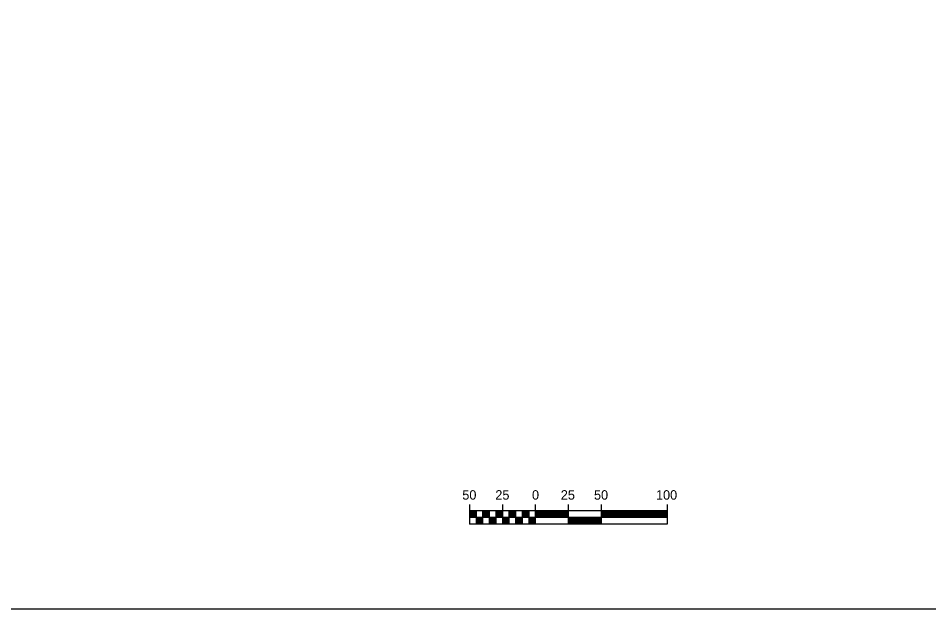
# Model space of a CAD drawing. Extents: x 1806834 to 1810084, y 678065 to 679314.
# Drawn here: x 1807616 to 1808308, y 678065 to 678514 of the extents above; entities that cross this region are included whole.
import ezdxf

# ---------------------------------------------------------------- set-up
doc = ezdxf.new("R2010")
doc.units = 0
doc.layers.add('Default', color=7, linetype='Continuous')
doc.layers.add('DSN_DRFT_Guideline-No-Plot', color=7, linetype='Continuous')

msp = doc.modelspace()

# ---------------------------------------------------------------- linework, layer by layer
at = {"layer": 'Default'}
for p, q in [((1807958.81, 678144.7), (1807958.81, 678129.7)), ((1807983.81, 678144.7), (1807983.81, 678129.7)), ((1808008.81, 678144.7), (1808008.81, 678129.7)), ((1808033.81, 678144.7), (1808033.81, 678129.7)), ((1808058.81, 678144.7), (1808058.81, 678129.7)), ((1808108.8, 678144.7), (1808108.8, 678129.7)), ((1808108.8, 678139.7), (1807958.81, 678139.7)), ((1807958.81, 678139.45), (1807963.81, 678139.45)), ((1807958.81, 678139.2), (1807963.81, 678139.2)), ((1807958.81, 678138.95), (1807963.81, 678138.95)), ((1807958.81, 678138.7), (1807963.81, 678138.7)), ((1807958.81, 678138.45), (1807963.81, 678138.45)), ((1807958.81, 678138.2), (1807963.81, 678138.2)), ((1807958.81, 678137.95), (1807963.81, 678137.95)), ((1807958.81, 678137.7), (1807963.81, 678137.7)), ((1807958.81, 678137.45), (1807963.81, 678137.45)), ((1807958.81, 678137.2), (1807963.81, 678137.2)), ((1807958.81, 678136.95), (1807963.81, 678136.95)), ((1807958.81, 678136.7), (1807963.81, 678136.7)), ((1807958.81, 678136.45), (1807963.81, 678136.45)), ((1807958.81, 678136.2), (1807963.81, 678136.2)), ((1807958.81, 678135.95), (1807963.81, 678135.95)), ((1807958.81, 678135.7), (1807963.81, 678135.7)), ((1807958.81, 678135.45), (1807963.81, 678135.45)), ((1807958.81, 678135.2), (1807963.81, 678135.2)), ((1807958.81, 678134.95), (1807963.81, 678134.95)), ((1808108.8, 678134.7), (1807958.81, 678134.7)), ((1807963.81, 678139.7), (1807963.81, 678129.7)), ((1807968.81, 678139.7), (1807968.81, 678129.7)), ((1807968.81, 678139.45), (1807973.81, 678139.45)), ((1807968.81, 678139.2), (1807973.81, 678139.2)), ((1807968.81, 678138.95), (1807973.81, 678138.95)), ((1807968.81, 678138.7), (1807973.81, 678138.7)), ((1807968.81, 678138.45), (1807973.81, 678138.45)), ((1807968.81, 678138.2), (1807973.81, 678138.2)), ((1807968.81, 678137.95), (1807973.81, 678137.95)), ((1807968.81, 678137.7), (1807973.81, 678137.7)), ((1807968.81, 678137.45), (1807973.81, 678137.45)), ((1807968.81, 678137.2), (1807973.81, 678137.2)), ((1807968.81, 678136.95), (1807973.81, 678136.95)), ((1807968.81, 678136.7), (1807973.81, 678136.7)), ((1807968.81, 678136.45), (1807973.81, 678136.45)), ((1807968.81, 678136.2), (1807973.81, 678136.2)), ((1807968.81, 678135.95), (1807973.81, 678135.95)), ((1807968.81, 678135.7), (1807973.81, 678135.7)), ((1807968.81, 678135.45), (1807973.81, 678135.45)), ((1807968.81, 678135.2), (1807973.81, 678135.2)), ((1807968.81, 678134.95), (1807973.81, 678134.95)), ((1807973.81, 678139.7), (1807973.81, 678129.7)), ((1807978.81, 678139.7), (1807978.81, 678129.7)), ((1807978.81, 678139.45), (1807983.81, 678139.45)), ((1807978.81, 678139.2), (1807983.81, 678139.2)), ((1807978.81, 678138.95), (1807983.81, 678138.95)), ((1807978.81, 678138.7), (1807983.81, 678138.7)), ((1807978.81, 678138.45), (1807983.81, 678138.45)), ((1807978.81, 678138.2), (1807983.81, 678138.2)), ((1807978.81, 678137.95), (1807983.81, 678137.95)), ((1807978.81, 678137.7), (1807983.81, 678137.7)), ((1807978.81, 678137.45), (1807983.81, 678137.45)), ((1807978.81, 678137.2), (1807983.81, 678137.2)), ((1807978.81, 678136.95), (1807983.81, 678136.95)), ((1807978.81, 678136.7), (1807983.81, 678136.7)), ((1807978.81, 678136.45), (1807983.81, 678136.45)), ((1807978.81, 678136.2), (1807983.81, 678136.2)), ((1807978.81, 678135.95), (1807983.81, 678135.95)), ((1807978.81, 678135.7), (1807983.81, 678135.7)), ((1807978.81, 678135.45), (1807983.81, 678135.45)), ((1807978.81, 678135.2), (1807983.81, 678135.2)), ((1807978.81, 678134.95), (1807983.81, 678134.95)), ((1807988.81, 678139.7), (1807988.81, 678129.7)), ((1807988.81, 678139.45), (1807993.81, 678139.45)), ((1807988.81, 678139.2), (1807993.81, 678139.2)), ((1807988.81, 678138.95), (1807993.81, 678138.95)), ((1807988.81, 678138.7), (1807993.81, 678138.7)), ((1807988.81, 678138.45), (1807993.81, 678138.45)), ((1807988.81, 678138.2), (1807993.81, 678138.2)), ((1807988.81, 678137.95), (1807993.81, 678137.95)), ((1807988.81, 678137.7), (1807993.81, 678137.7)), ((1807988.81, 678137.45), (1807993.81, 678137.45)), ((1807988.81, 678137.2), (1807993.81, 678137.2)), ((1807988.81, 678136.95), (1807993.81, 678136.95)), ((1807988.81, 678136.7), (1807993.81, 678136.7)), ((1807988.81, 678136.45), (1807993.81, 678136.45)), ((1807988.81, 678136.2), (1807993.81, 678136.2)), ((1807988.81, 678135.95), (1807993.81, 678135.95)), ((1807988.81, 678135.7), (1807993.81, 678135.7)), ((1807988.81, 678135.45), (1807993.81, 678135.45)), ((1807988.81, 678135.2), (1807993.81, 678135.2)), ((1807988.81, 678134.95), (1807993.81, 678134.95)), ((1807993.81, 678139.7), (1807993.81, 678129.7)), ((1807998.81, 678139.7), (1807998.81, 678129.7)), ((1807998.81, 678139.45), (1808003.81, 678139.45)), ((1807998.81, 678139.2), (1808003.81, 678139.2)), ((1807998.81, 678138.95), (1808003.81, 678138.95)), ((1807998.81, 678138.7), (1808003.81, 678138.7)), ((1807998.81, 678138.45), (1808003.81, 678138.45)), ((1807998.81, 678138.2), (1808003.81, 678138.2)), ((1807998.81, 678137.95), (1808003.81, 678137.95)), ((1807998.81, 678137.7), (1808003.81, 678137.7)), ((1807998.81, 678137.45), (1808003.81, 678137.45)), ((1807998.81, 678137.2), (1808003.81, 678137.2)), ((1807998.81, 678136.95), (1808003.81, 678136.95)), ((1807998.81, 678136.7), (1808003.81, 678136.7)), ((1807998.81, 678136.45), (1808003.81, 678136.45)), ((1807998.81, 678136.2), (1808003.81, 678136.2)), ((1807998.81, 678135.95), (1808003.81, 678135.95)), ((1807998.81, 678135.7), (1808003.81, 678135.7)), ((1807998.81, 678135.45), (1808003.81, 678135.45)), ((1807998.81, 678135.2), (1808003.81, 678135.2)), ((1807998.81, 678134.95), (1808003.81, 678134.95)), ((1808003.81, 678139.7), (1808003.81, 678129.7)), ((1808033.81, 678139.45), (1808008.81, 678139.45)), ((1808033.81, 678139.2), (1808008.81, 678139.2)), ((1808033.81, 678138.95), (1808008.81, 678138.95)), ((1808033.81, 678138.7), (1808008.81, 678138.7)), ((1808033.81, 678138.45), (1808008.81, 678138.45)), ((1808033.81, 678138.2), (1808008.81, 678138.2)), ((1808033.81, 678137.95), (1808008.81, 678137.95)), ((1808033.81, 678137.7), (1808008.81, 678137.7)), ((1808033.81, 678137.45), (1808008.81, 678137.45)), ((1808033.81, 678137.2), (1808008.81, 678137.2)), ((1808033.81, 678136.95), (1808008.81, 678136.95)), ((1808033.81, 678136.7), (1808008.81, 678136.7)), ((1808033.81, 678136.45), (1808008.81, 678136.45)), ((1808033.81, 678136.2), (1808008.81, 678136.2)), ((1808033.81, 678135.95), (1808008.81, 678135.95)), ((1808033.81, 678135.7), (1808008.81, 678135.7)), ((1808033.81, 678135.45), (1808008.81, 678135.45)), ((1808033.81, 678135.2), (1808008.81, 678135.2)), ((1808033.81, 678134.95), (1808008.81, 678134.95)), ((1808058.81, 678139.45), (1808108.8, 678139.45)), ((1808058.81, 678139.2), (1808108.8, 678139.2)), ((1808058.81, 678138.95), (1808108.8, 678138.95)), ((1808058.81, 678138.7), (1808108.8, 678138.7)), ((1808058.81, 678138.45), (1808108.8, 678138.45)), ((1808058.81, 678138.2), (1808108.8, 678138.2)), ((1808058.81, 678137.95), (1808108.8, 678137.95)), ((1808058.81, 678137.7), (1808108.8, 678137.7)), ((1808058.81, 678137.45), (1808108.8, 678137.45)), ((1808058.81, 678137.2), (1808108.8, 678137.2)), ((1808058.81, 678136.95), (1808108.8, 678136.95)), ((1808058.81, 678136.7), (1808108.8, 678136.7)), ((1808058.81, 678136.45), (1808108.8, 678136.45)), ((1808058.81, 678136.2), (1808108.8, 678136.2)), ((1808058.81, 678135.95), (1808108.8, 678135.95)), ((1808058.81, 678135.7), (1808108.8, 678135.7)), ((1808058.81, 678135.45), (1808108.8, 678135.45)), ((1808058.81, 678135.2), (1808108.8, 678135.2)), ((1808058.81, 678134.95), (1808108.8, 678134.95)), ((1808108.8, 678129.7), (1807958.81, 678129.7)), ((1807963.81, 678134.45), (1807968.81, 678134.45)), ((1807963.81, 678134.2), (1807968.81, 678134.2)), ((1807963.81, 678133.95), (1807968.81, 678133.95)), ((1807963.81, 678133.7), (1807968.81, 678133.7)), ((1807963.81, 678133.45), (1807968.81, 678133.45)), ((1807963.81, 678133.2), (1807968.81, 678133.2)), ((1807963.81, 678132.95), (1807968.81, 678132.95)), ((1807963.81, 678132.7), (1807968.81, 678132.7)), ((1807963.81, 678132.45), (1807968.81, 678132.45)), ((1807963.81, 678132.2), (1807968.81, 678132.2)), ((1807963.81, 678131.95), (1807968.81, 678131.95)), ((1807963.81, 678131.7), (1807968.81, 678131.7)), ((1807963.81, 678131.45), (1807968.81, 678131.45)), ((1807963.81, 678131.2), (1807968.81, 678131.2)), ((1807963.81, 678130.95), (1807968.81, 678130.95)), ((1807963.81, 678130.7), (1807968.81, 678130.7)), ((1807963.81, 678130.45), (1807968.81, 678130.45)), ((1807963.81, 678130.2), (1807968.81, 678130.2)), ((1807963.81, 678129.95), (1807968.81, 678129.95)), ((1807973.81, 678134.45), (1807978.81, 678134.45)), ((1807973.81, 678134.2), (1807978.81, 678134.2)), ((1807973.81, 678133.95), (1807978.81, 678133.95)), ((1807973.81, 678133.7), (1807978.81, 678133.7)), ((1807973.81, 678133.45), (1807978.81, 678133.45)), ((1807973.81, 678133.2), (1807978.81, 678133.2)), ((1807973.81, 678132.95), (1807978.81, 678132.95)), ((1807973.81, 678132.7), (1807978.81, 678132.7)), ((1807973.81, 678132.45), (1807978.81, 678132.45)), ((1807973.81, 678132.2), (1807978.81, 678132.2)), ((1807973.81, 678131.95), (1807978.81, 678131.95)), ((1807973.81, 678131.7), (1807978.81, 678131.7)), ((1807973.81, 678131.45), (1807978.81, 678131.45)), ((1807973.81, 678131.2), (1807978.81, 678131.2)), ((1807973.81, 678130.95), (1807978.81, 678130.95)), ((1807973.81, 678130.7), (1807978.81, 678130.7)), ((1807973.81, 678130.45), (1807978.81, 678130.45)), ((1807973.81, 678130.2), (1807978.81, 678130.2)), ((1807973.81, 678129.95), (1807978.81, 678129.95)), ((1807983.81, 678134.45), (1807988.81, 678134.45)), ((1807983.81, 678134.2), (1807988.81, 678134.2)), ((1807983.81, 678133.95), (1807988.81, 678133.95)), ((1807983.81, 678133.7), (1807988.81, 678133.7)), ((1807983.81, 678133.45), (1807988.81, 678133.45)), ((1807983.81, 678133.2), (1807988.81, 678133.2)), ((1807983.81, 678132.95), (1807988.81, 678132.95)), ((1807983.81, 678132.7), (1807988.81, 678132.7)), ((1807983.81, 678132.45), (1807988.81, 678132.45)), ((1807983.81, 678132.2), (1807988.81, 678132.2)), ((1807983.81, 678131.95), (1807988.81, 678131.95)), ((1807983.81, 678131.7), (1807988.81, 678131.7)), ((1807983.81, 678131.45), (1807988.81, 678131.45)), ((1807983.81, 678131.2), (1807988.81, 678131.2)), ((1807983.81, 678130.95), (1807988.81, 678130.95)), ((1807983.81, 678130.7), (1807988.81, 678130.7)), ((1807983.81, 678130.45), (1807988.81, 678130.45)), ((1807983.81, 678130.2), (1807988.81, 678130.2)), ((1807983.81, 678129.95), (1807988.81, 678129.95)), ((1807993.81, 678134.45), (1807998.81, 678134.45)), ((1807993.81, 678134.2), (1807998.81, 678134.2)), ((1807993.81, 678133.95), (1807998.81, 678133.95)), ((1807993.81, 678133.7), (1807998.81, 678133.7)), ((1807993.81, 678133.45), (1807998.81, 678133.45)), ((1807993.81, 678133.2), (1807998.81, 678133.2)), ((1807993.81, 678132.95), (1807998.81, 678132.95)), ((1807993.81, 678132.7), (1807998.81, 678132.7)), ((1807993.81, 678132.45), (1807998.81, 678132.45)), ((1807993.81, 678132.2), (1807998.81, 678132.2)), ((1807993.81, 678131.95), (1807998.81, 678131.95)), ((1807993.81, 678131.7), (1807998.81, 678131.7)), ((1807993.81, 678131.45), (1807998.81, 678131.45)), ((1807993.81, 678131.2), (1807998.81, 678131.2)), ((1807993.81, 678130.95), (1807998.81, 678130.95)), ((1807993.81, 678130.7), (1807998.81, 678130.7)), ((1807993.81, 678130.45), (1807998.81, 678130.45)), ((1807993.81, 678130.2), (1807998.81, 678130.2)), ((1807993.81, 678129.95), (1807998.81, 678129.95)), ((1808003.81, 678134.45), (1808008.81, 678134.45)), ((1808003.81, 678134.2), (1808008.81, 678134.2)), ((1808003.81, 678133.95), (1808008.81, 678133.95)), ((1808003.81, 678133.7), (1808008.81, 678133.7)), ((1808003.81, 678133.45), (1808008.81, 678133.45)), ((1808003.81, 678133.2), (1808008.81, 678133.2)), ((1808003.81, 678132.95), (1808008.81, 678132.95)), ((1808003.81, 678132.7), (1808008.81, 678132.7)), ((1808003.81, 678132.45), (1808008.81, 678132.45)), ((1808003.81, 678132.2), (1808008.81, 678132.2)), ((1808003.81, 678131.95), (1808008.81, 678131.95)), ((1808003.81, 678131.7), (1808008.81, 678131.7)), ((1808003.81, 678131.45), (1808008.81, 678131.45)), ((1808003.81, 678131.2), (1808008.81, 678131.2)), ((1808003.81, 678130.95), (1808008.81, 678130.95)), ((1808003.81, 678130.7), (1808008.81, 678130.7)), ((1808003.81, 678130.45), (1808008.81, 678130.45)), ((1808003.81, 678130.2), (1808008.81, 678130.2)), ((1808003.81, 678129.95), (1808008.81, 678129.95)), ((1808058.81, 678134.45), (1808033.81, 678134.45)), ((1808058.81, 678134.2), (1808033.81, 678134.2)), ((1808058.81, 678133.95), (1808033.81, 678133.95)), ((1808058.81, 678133.7), (1808033.81, 678133.7)), ((1808058.81, 678133.45), (1808033.81, 678133.45)), ((1808058.81, 678133.2), (1808033.81, 678133.2)), ((1808058.81, 678132.95), (1808033.81, 678132.95)), ((1808058.81, 678132.7), (1808033.81, 678132.7)), ((1808058.81, 678132.45), (1808033.81, 678132.45)), ((1808058.81, 678132.2), (1808033.81, 678132.2)), ((1808058.81, 678131.95), (1808033.81, 678131.95)), ((1808058.81, 678131.7), (1808033.81, 678131.7)), ((1808058.81, 678131.45), (1808033.81, 678131.45)), ((1808058.81, 678131.2), (1808033.81, 678131.2)), ((1808058.81, 678130.95), (1808033.81, 678130.95)), ((1808058.81, 678130.7), (1808033.81, 678130.7)), ((1808058.81, 678130.45), (1808033.81, 678130.45)), ((1808058.81, 678130.2), (1808033.81, 678130.2)), ((1808058.81, 678129.95), (1808033.81, 678129.95))]:
    msp.add_line(p, q, dxfattribs=at)
at = {"layer": 'DSN_DRFT_Guideline-No-Plot'}
msp.add_lwpolyline([(1806833.89, 678065.46), (1808483.89, 678065.46), (1808483.89, 679064.52), (1806833.89, 679064.52)], close=True, dxfattribs=at)

# ---------------------------------------------------------------- texts
at = {"layer": 'Default'}
for s, p in [('50', (1807953.37, 678148.25)), ('25', (1807978.46, 678148.25)), ('0', (1808006.29, 678148.25)), ('25', (1808028.16, 678148.25)), ('50', (1808053.36, 678148.25)), ('100', (1808100.44, 678148.25))]:
    msp.add_text(s, height=7.2, dxfattribs=at).set_placement(p)

doc.saveas('drawing.dxf')
